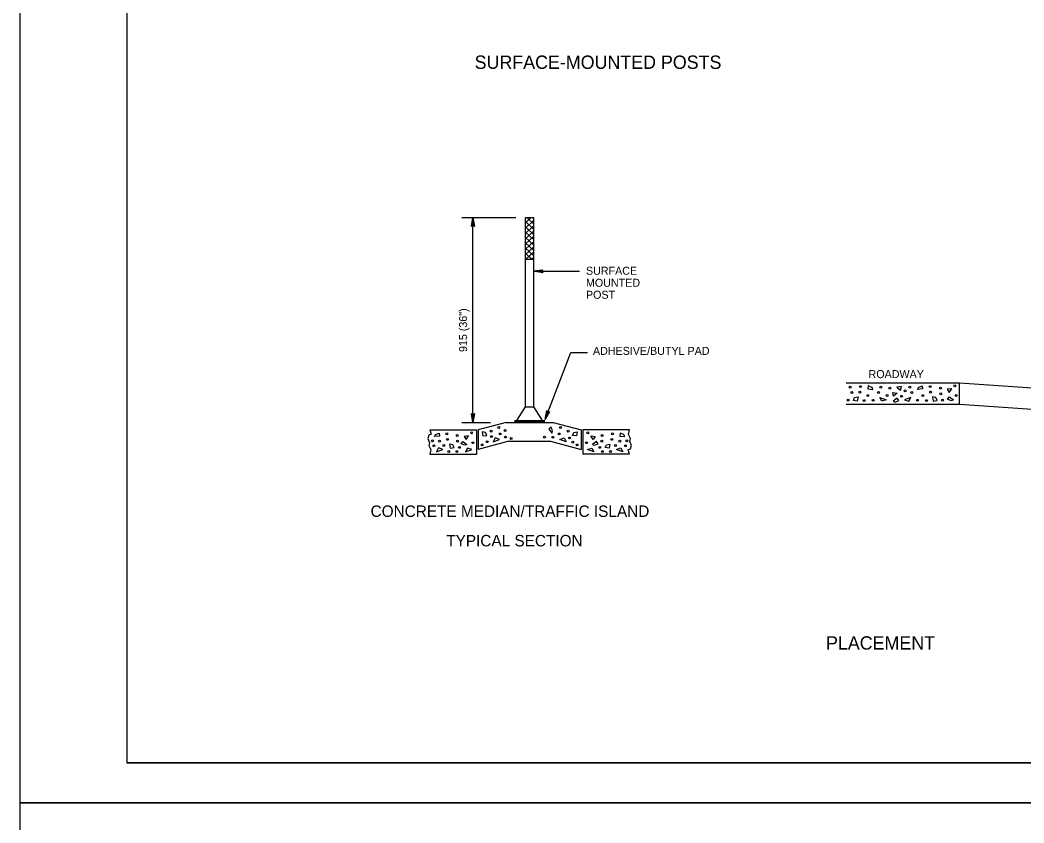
# Model space of a CAD drawing. Extents: x 640253 to 641999, y 298458 to 299646.
# Drawn here: x 640253.3 to 640629.6, y 299044.1 to 299344.9 of the extents above; entities that cross this region are included whole.
import ezdxf

# ---------------------------------------------------------------- set-up
doc = ezdxf.new("R2010")
doc.units = 0
for name, color, linetype in [('1', 7, 'Continuous'), ('2', 7, 'Continuous'), ('PLT-BNDY', 7, 'Continuous')]:
    doc.layers.add(name, color=color, linetype=linetype)

msp = doc.modelspace()

# ---------------------------------------------------------------- linework, layer by layer
at = {"layer": '1'}
for p, q in [((640293.31, 299630.63), (640293.31, 299066.63)), ((641079.31, 299066.63), (640293.31, 299066.63)), ((640293.31, 299066.63), (640879.31, 299066.63))]:
    msp.add_line(p, q, dxfattribs=at)
at = {"layer": '2'}
for p, q in [((640418.89, 299270.87), (640439.12, 299270.87)), ((640423.06, 299194.13), (640423.06, 299270.87)), ((640442.69, 299270.87), (640445.92, 299270.87)), ((640442.69, 299255.28), (640442.69, 299270.87)), ((640442.69, 299268.93), (640444.82, 299270.87)), ((640442.69, 299266.95), (640445.92, 299269.89)), ((640445.92, 299266.46), (640442.69, 299269.4)), ((640445.92, 299268.43), (640443.24, 299270.87)), ((640445.92, 299270.41), (640445.42, 299270.87)), ((640445.92, 299255.28), (640445.92, 299270.87)), ((640442.69, 299264.97), (640445.92, 299267.91)), ((640445.92, 299264.47), (640442.69, 299267.41)), ((640442.69, 299262.99), (640445.92, 299265.93)), ((640445.92, 299262.5), (640442.69, 299265.43)), ((640442.69, 299261.01), (640445.92, 299263.95)), ((640445.92, 299260.51), (640442.69, 299263.45)), ((640442.69, 299259.03), (640445.92, 299261.97)), ((640445.92, 299258.53), (640442.69, 299261.47)), ((640442.69, 299257.05), (640445.92, 299259.99)), ((640445.92, 299256.55), (640442.69, 299259.49)), ((640445.14, 299255.28), (640442.69, 299257.52)), ((640442.96, 299255.28), (640442.69, 299255.53)), ((640442.69, 299255.28), (640445.92, 299255.28)), ((640442.69, 299200.02), (640442.69, 299255.28)), ((640442.92, 299255.28), (640445.92, 299258.01)), ((640445.1, 299255.28), (640445.92, 299256.03)), ((640445.92, 299200.02), (640445.92, 299255.28)), ((640445.92, 299250.8), (640463, 299250.8)), ((640450.08, 299195.24), (640459.71, 299220.35)), ((640459.71, 299220.35), (640465.99, 299220.35)), ((640562.97, 299208.99), (640605.44, 299208.99)), ((640605.44, 299200.94), (640605.44, 299208.99)), ((640605.44, 299208.99), (640714.64, 299201.64)), ((640439.54, 299194.82), (640442.69, 299200.02)), ((640442.69, 299200.02), (640445.92, 299200.02)), ((640449.07, 299194.82), (640445.92, 299200.02)), ((640562.97, 299200.94), (640605.44, 299200.94)), ((640605.44, 299200.94), (640714.64, 299193.59)), ((640418.89, 299194.13), (640429.65, 299194.13)), ((640435.56, 299194.13), (640425.06, 299191.32)), ((640435.56, 299194.13), (640453.06, 299194.13)), ((640438.66, 299194.65), (640449.95, 299194.65)), ((640438.66, 299194.48), (640449.95, 299194.48)), ((640438.66, 299194.31), (640449.95, 299194.31)), ((640438.67, 299194.82), (640449.94, 299194.82)), ((640453.06, 299194.13), (640463.56, 299191.32)), ((640406.86, 299191.32), (640424.36, 299191.32)), ((640424.36, 299191.32), (640424.36, 299182.32)), ((640425.06, 299191.32), (640425.06, 299184.07)), ((640463.56, 299191.32), (640463.56, 299184.07)), ((640464.26, 299191.32), (640464.26, 299182.32)), ((640481.76, 299191.32), (640464.26, 299191.32)), ((640436.49, 299187.13), (640425.06, 299184.07)), ((640436.49, 299187.13), (640452.13, 299187.13)), ((640452.13, 299187.13), (640463.56, 299184.07)), ((640406.86, 299182.32), (640424.36, 299182.32)), ((640481.76, 299182.32), (640464.26, 299182.32))]:
    msp.add_line(p, q, dxfattribs=at)
for points in [[(640422.66, 299267.67), (640422.89, 299267.79), (640423.06, 299270.87), (640422.66, 299267.67), (640422.52, 299267.51), (640423.06, 299270.87), (640423.21, 299267.79), (640423.44, 299267.68), (640423.06, 299270.87), (640423.6, 299267.51), (640423.44, 299267.68)], [(640449.12, 299250.39), (640449, 299250.62), (640445.92, 299250.8), (640449.12, 299250.39), (640449.28, 299250.25), (640445.92, 299250.8), (640449, 299250.95), (640449.11, 299251.17), (640445.92, 299250.8), (640449.28, 299251.33), (640449.11, 299251.17)], [(640451.6, 299198.07), (640451.34, 299198.05), (640450.08, 299195.24), (640451.6, 299198.07), (640451.79, 299198.18), (640450.08, 299195.24), (640451.04, 299198.16), (640450.87, 299198.35), (640450.08, 299195.24), (640450.78, 299198.56), (640450.87, 299198.35)], [(640423.46, 299197.33), (640423.23, 299197.21), (640423.06, 299194.13), (640423.46, 299197.33), (640423.6, 299197.49), (640423.06, 299194.13), (640422.91, 299197.21), (640422.68, 299197.32), (640423.06, 299194.13), (640422.53, 299197.49), (640422.68, 299197.32)], [(640406.86, 299191.32), (640407.34, 299189.77), (640406.52, 299189.35), (640406.11, 299188.12), (640406.73, 299186.57), (640406.52, 299185.54), (640407.24, 299184), (640406.86, 299182.32)], [(640481.76, 299182.32), (640481.27, 299183.88), (640482.09, 299184.29), (640482.5, 299185.52), (640481.88, 299187.07), (640482.09, 299188.1), (640481.37, 299189.65), (640481.76, 299191.32)]]:
    msp.add_lwpolyline(points, dxfattribs=at)
for points in [[(640572.62, 299207.3), (640571.23, 299207.85), (640571.09, 299206.73), (640572.96, 299206.53)], [(640583.33, 299206.25), (640583.63, 299207.63), (640581.96, 299207.34)], [(640590.06, 299207.3), (640591.45, 299207.85), (640591.59, 299206.73), (640589.72, 299206.53)], [(640600.78, 299206.59), (640601.54, 299205.41), (640602.52, 299206.8)], [(640567.08, 299202.17), (640565.63, 299202.37), (640566.11, 299203.48), (640567.37, 299203.69)], [(640577.93, 299202.64), (640576.27, 299202.09), (640575.57, 299203.55)], [(640580.68, 299203.99), (640580.39, 299205.37), (640582.06, 299205.07)], [(640581.34, 299201.76), (640582.71, 299202.35), (640582.02, 299203.23), (640580.55, 299202.06)], [(640584.74, 299202.64), (640586.41, 299202.09), (640587.11, 299203.55)], [(640595.59, 299202.17), (640597.05, 299202.37), (640596.57, 299203.48), (640595.31, 299203.69)], [(640602.33, 299202.27), (640600.96, 299202.86), (640601.65, 299203.75), (640603.12, 299202.57)], [(640426.76, 299189.08), (640428.21, 299189.28), (640427.73, 299190.4), (640426.48, 299190.6)], [(640452.9, 299190.96), (640452.31, 299192.33), (640451.43, 299191.65), (640452.6, 299190.17)], [(640461.86, 299189.08), (640460.4, 299189.28), (640460.88, 299190.4), (640462.13, 299190.6)], [(640408.98, 299189.62), (640410.37, 299190.18), (640410.51, 299189.06), (640408.63, 299188.86)], [(640419.96, 299185.58), (640418.59, 299186.17), (640419.27, 299187.06), (640420.75, 299185.88)], [(640419.7, 299188.92), (640420.46, 299187.74), (640421.43, 299189.13)], [(640433.01, 299187.82), (640431.34, 299188.37), (640430.65, 299186.91)], [(640455.61, 299187.82), (640457.27, 299188.37), (640457.97, 299186.91)], [(640468.92, 299188.92), (640468.15, 299187.74), (640467.18, 299189.13)], [(640468.65, 299185.58), (640470.02, 299186.17), (640469.34, 299187.06), (640467.86, 299185.88)], [(640479.63, 299189.62), (640478.25, 299190.18), (640478.1, 299189.06), (640479.98, 299188.86)], [(640411.75, 299184.05), (640410.08, 299184.61), (640409.38, 299183.15)], [(640414.51, 299184.49), (640415.97, 299184.7), (640415.48, 299185.81), (640414.23, 299186.02)], [(640422.61, 299184), (640420.95, 299184.56), (640420.25, 299183.1)], [(640466, 299184), (640467.67, 299184.56), (640468.36, 299183.1)], [(640474.1, 299184.49), (640472.65, 299184.7), (640473.13, 299185.81), (640474.38, 299186.02)], [(640476.86, 299184.05), (640478.53, 299184.61), (640479.23, 299183.15)]]:
    msp.add_lwpolyline(points, close=True, dxfattribs=at)
for centre in [(640564.41, 299207.36), (640565.11, 299205.35), (640568.1, 299205.48), (640568.32, 299207.56), (640575.09, 299205.35), (640575.9, 299207.33), (640579.29, 299207.02), (640585.06, 299205.95), (640586.78, 299207.33), (640587.58, 299205.35), (640594.36, 299207.56), (640594.58, 299205.48), (640598.26, 299206.95), (640603.65, 299207.9), (640563.64, 299202.48), (640569.63, 299202.32), (640571, 299204.18), (640573.06, 299202.44), (640578.32, 299204.24), (640583.7, 299203.94), (640589.62, 299202.44), (640591.67, 299204.18), (640593.05, 299202.32), (640598.39, 299204.83), (640599.04, 299202.48), (640604.11, 299204.24), (640422.57, 299190.23), (640429.82, 299190.9), (640432.7, 299192.29), (640435.07, 299191.16), (640455.91, 299192.29), (640458.79, 299190.9), (640466.05, 299190.23), (640407.84, 299187.27), (640410.49, 299187.12), (640413.27, 299189.89), (640413.5, 299187.81), (640417.18, 299189.28), (640417.3, 299187.16), (640423.03, 299186.57), (640428.38, 299186.93), (640430.03, 299188.84), (640433.22, 299189.82), (640435.22, 299188.68), (640437.33, 299188.12), (640449.84, 299188.63), (640452.98, 299188.58), (640455.4, 299189.82), (640459.2, 299188.33), (640460.44, 299186.73), (640465.59, 299186.57), (640471.31, 299187.16), (640471.43, 299189.28), (640475.12, 299187.81), (640475.34, 299189.89), (640478.12, 299187.12), (640480.77, 299187.27), (640408.44, 299185.43), (640412.17, 299185.48), (640413.97, 299183.26), (640417.06, 299183.21), (640417.96, 299184.81), (640426.53, 299185.7), (640462.09, 299185.7), (640470.65, 299184.81), (640471.56, 299183.21), (640474.64, 299183.26), (640476.44, 299185.48), (640480.18, 299185.43)]:
    msp.add_circle(centre, 0.352, dxfattribs=at)
at = {"layer": 'PLT-BNDY'}
for points in [[(640253.31, 299645.63), (641094.31, 299645.63), (641094.31, 299051.63), (640253.31, 299051.63)], [(640253.31, 299051.63), (641094.31, 299051.63), (641094.31, 298457.63), (640253.31, 298457.63)]]:
    msp.add_lwpolyline(points, close=True, dxfattribs=at)

# ---------------------------------------------------------------- texts
at = {"layer": '2'}
for s, height, p in [('SURFACE-MOUNTED POSTS', 5, (640423.68, 299326.6)), ('SURFACE', 3, (640465.41, 299249.48)), ('MOUNTED', 3, (640465.41, 299244.98)), ('POST', 3, (640465.41, 299240.48)), ('ADHESIVE/BUTYL PAD', 3, (640468.03, 299219.46)), ('ROADWAY', 3, (640571.33, 299210.76)), ('CONCRETE MEDIAN/TRAFFIC ISLAND', 4.3, (640384.69, 299158.75)), ('TYPICAL SECTION', 4.3, (640413.04, 299147.71)), ('PLACEMENT', 5, (640555.38, 299109.04))]:
    msp.add_text(s, height=height, dxfattribs=at).set_placement(p)
msp.add_text('915 (36")', height=3, rotation=90, dxfattribs=at).set_placement((640420.86, 299220.52))

doc.saveas('drawing.dxf')
